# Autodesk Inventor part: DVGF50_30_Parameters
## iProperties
Created: 2010-04
Part Number: DVGF50_30_Parameters
Document SubType Name: Modeling
Designer: TB
Density: 1 g/cm^3
Slaglengde: 100.000 mm
Vinkel_Plussport: 0.00 deg
Vinkel_Minusport: 0.00 deg
Forlengelse_rør: 0.000 mm
Author: TB
